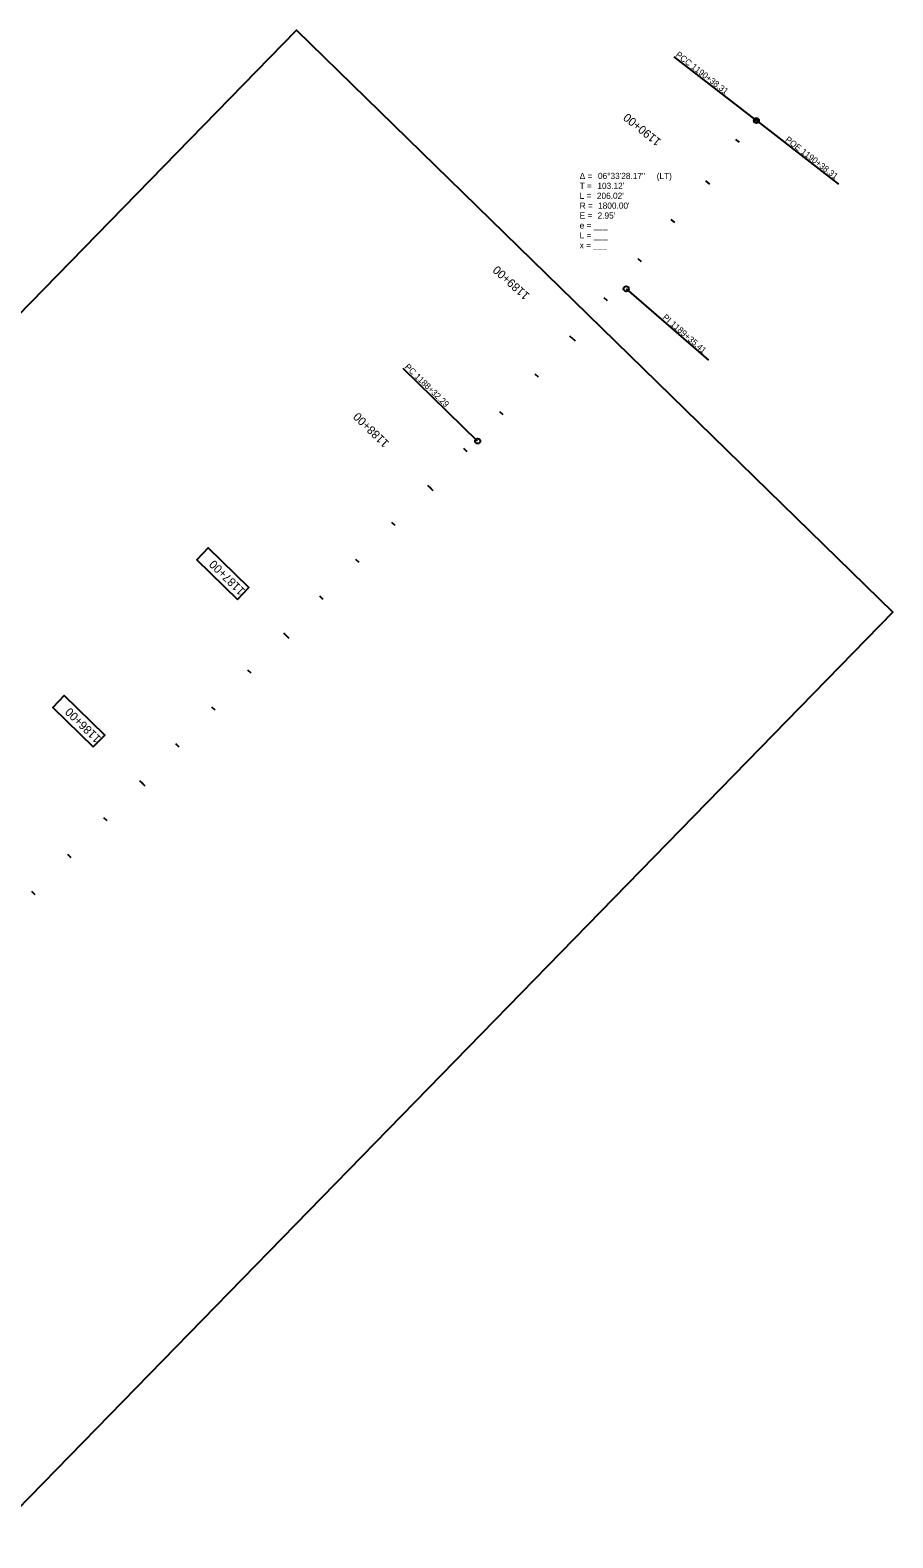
# Model space of a CAD drawing. Extents: x 19420655 to 19421801, y 7630893 to 7632053.
# Drawn here: x 19421383 to 19421801, y 7631322 to 7632053 of the extents above; entities that cross this region are included whole.
import ezdxf

# ---------------------------------------------------------------- set-up
doc = ezdxf.new("R2010")
doc.units = 0
for name, color, linetype in [('Level 1', 7, 'Continuous'), ('Level 3', 7, 'Continuous'), ('Level 4', 7, 'Continuous'), ('Level 5', 7, 'Continuous'), ('Level 6', 7, 'Continuous')]:
    doc.layers.add(name, color=color, linetype=linetype)

msp = doc.modelspace()

# ---------------------------------------------------------------- linework, layer by layer
at = {"layer": 'Level 1'}
for p, q in [((19421709.9, 7631980.1), (19421711.8, 7631978.56)), ((19421645.85, 7631903.36), (19421644.23, 7631904.82)), ((19421576.93, 7631830.91), (19421575.37, 7631832.43)), ((19421507.09, 7631759.34), (19421505.53, 7631760.86)), ((19421437.25, 7631687.77), (19421435.69, 7631689.29))]:
    msp.add_line(p, q, dxfattribs=at)
at = {"layer": 'Level 3'}
for p, q in [((19421734.62, 7632009.37), (19421694.76, 7632040.22)), ((19421694.76, 7632040.22), (19421694.76, 7632040.22)), ((19421734.62, 7632009.37), (19421774.47, 7631978.52)), ((19421774.47, 7631978.52), (19421774.47, 7631978.52)), ((19421671.5, 7631927.82), (19421711.33, 7631893.17)), ((19421711.33, 7631893.17), (19421711.33, 7631893.17)), ((19421599.48, 7631854.01), (19421563.41, 7631889.21)), ((19421563.41, 7631889.21), (19421563.41, 7631889.21))]:
    msp.add_line(p, q, dxfattribs=at)
for centre, radius in [((19421734.62, 7632009.37), 1.25), ((19421734.62, 7632009.37), 1.07), ((19421671.5, 7631927.82), 1.25), ((19421599.48, 7631854.01), 1.25)]:
    msp.add_circle(centre, radius, dxfattribs=at)
at = {"layer": 'Level 4'}
for p, q in [((19421726.44, 7631998.88), (19421724.72, 7632000.23)), ((19421709.9, 7631980.1), (19421711.8, 7631978.56)), ((19421695, 7631960), (19421693.32, 7631961.39)), ((19421678.88, 7631940.89), (19421677.22, 7631942.31)), ((19421662.49, 7631922.01), (19421660.85, 7631923.45)), ((19421644.94, 7631904.18), (19421646.75, 7631902.53)), ((19421628.94, 7631884.94), (19421627.34, 7631886.42)), ((19421611.79, 7631866.75), (19421610.21, 7631868.26)), ((19421594.39, 7631848.8), (19421592.83, 7631850.33)), ((19421576.05, 7631831.76), (19421577.8, 7631830.05)), ((19421559.47, 7631813.01), (19421557.91, 7631814.54)), ((19421542.01, 7631795.12), (19421540.45, 7631796.65)), ((19421524.55, 7631777.23), (19421522.99, 7631778.75)), ((19421506.21, 7631760.19), (19421507.96, 7631758.48)), ((19421489.63, 7631741.44), (19421488.07, 7631742.97)), ((19421472.17, 7631723.55), (19421470.61, 7631725.08)), ((19421454.71, 7631705.66), (19421453.15, 7631707.18)), ((19421436.37, 7631688.62), (19421438.12, 7631686.91)), ((19421419.79, 7631669.87), (19421418.23, 7631671.4)), ((19421402.33, 7631651.98), (19421400.76, 7631653.51)), ((19421384.87, 7631634.09), (19421383.3, 7631635.61))]:
    msp.add_line(p, q, dxfattribs=at)
at = {"layer": 'Level 5'}
msp.add_lwpolyline([(19421073.73, 7631604.47), (19421511.62, 7632053.22), (19421800.77, 7631771.06), (19421362.87, 7631322.32)], close=True, dxfattribs=at)
at = {"layer": 'Level 6'}
for points in [[(19421482.98, 7631777.28), (19421488.56, 7631783), (19421468.88, 7631802.21), (19421463.29, 7631796.48)], [(19421413.13, 7631705.71), (19421418.72, 7631711.43), (19421399.04, 7631730.64), (19421393.45, 7631724.91)]]:
    msp.add_lwpolyline(points, close=True, dxfattribs=at)

# ---------------------------------------------------------------- texts
at = {"layer": 'Level 1'}
msp.add_text('1190+00', height=4.08, rotation=141.03957, dxfattribs=at).set_placement((19421688.81, 7631999.78))
at = {"layer": 'Level 3'}
for s, rotation, p in [('PCC', 322.25886, (19421695.17, 7632040.74)), ('1190+38.31', 322.25886, (19421702.71, 7632034.9)), ('POE ', 322.25886, (19421748.31, 7631999.6)), ('1190+38.31', 322.25886, (19421755.92, 7631993.71)), ('PI ', 318.97995, (19421688.88, 7631913.57)), ('1189+35.41', 318.97995, (19421692.66, 7631910.28)), ('PC', 315.70104, (19421563.86, 7631889.68)), ('1188+32.29', 315.70104, (19421568.63, 7631885.03))]:
    msp.add_text(s, height=3, rotation=rotation, dxfattribs=at).set_placement(p)
for s, p in [('Δ = ', (19421648.94, 7631981.04)), ('06°33\'28.17"', (19421657.82, 7631981.04)), (' (LT)', (19421685.16, 7631981.04)), ('T = ', (19421648.94, 7631976.24)), ('L = ', (19421648.94, 7631971.44)), ("206.02'", (19421657.3, 7631971.44)), ("103.12'", (19421657.52, 7631976.24)), ('R = ', (19421648.94, 7631966.64)), ("1800.00'", (19421657.87, 7631966.64)), ('e = ___ ', (19421648.94, 7631957.04)), ('E = ', (19421648.94, 7631961.84)), ("2.95'", (19421657.61, 7631961.84)), ('L = ___', (19421648.94, 7631952.24)), ('x = ___', (19421648.94, 7631947.44))]:
    msp.add_text(s, height=3, dxfattribs=at).set_placement(p)
at = {"layer": 'Level 4'}
for s, rotation, p in [('1190+00', 141.03957, (19421688.81, 7631999.78)), ('1189+00', 137.85647, (19421624.97, 7631925)), ('1188+00', 135.70104, (19421556.88, 7631853.32)), ('1187+00', 135.70104, (19421487.04, 7631781.75)), ('1186+00', 135.70104, (19421417.2, 7631710.18))]:
    msp.add_text(s, height=4.08, rotation=rotation, dxfattribs=at).set_placement(p)

doc.saveas('drawing.dxf')
